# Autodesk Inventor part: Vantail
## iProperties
Shininess: 20.0
Length Units: 11269
Angle Units: 11279
Time Units: 11290
Mass Units: 11283
Length Display Precision: 3
Angle Display Precision: 2
Part Number: Vantail
Material: Par défaut
Document SubType Name: Modeling
Created: 2007-01
Designer: plantier
Density: 0.0
Volumn: 0.0
Area: 0.0
PropertySet Name: Model Information
Control State: 0
Master: False
Checked Out: False
Author: plantier
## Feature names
1. Extrusion1
2. Extrusion2
3. Réseau rectangulaire1 [Rectangular Pattern]
4. Extrusion3
5. Congé1 [Fillet]
6. Réseau rectangulaire2 [Rectangular Pattern]
7. Balayage1
8. Extrusion5
